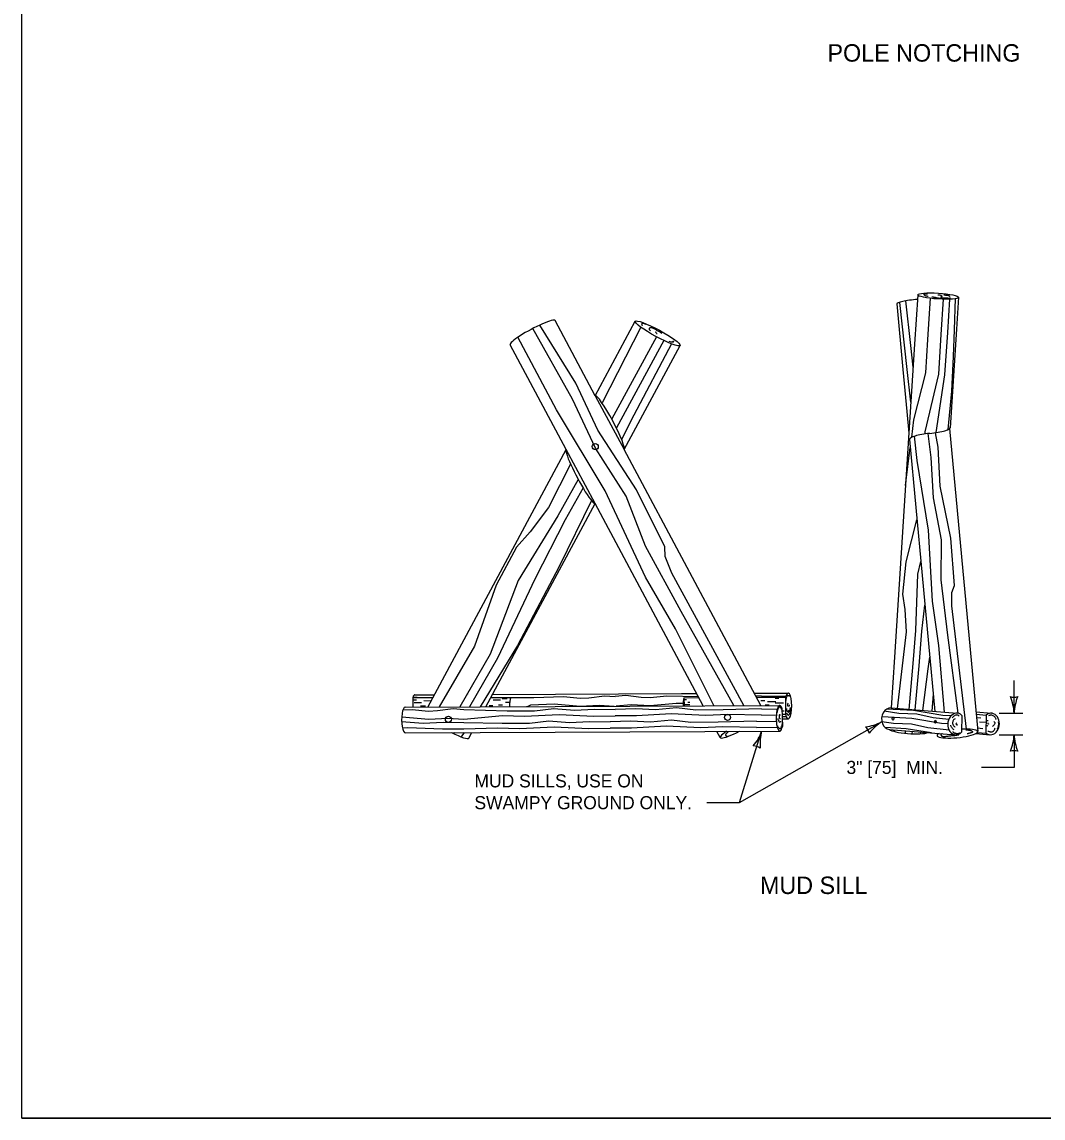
# Model space of a CAD drawing. Extents: x 49991.4 to 50021, y 49987.6 to 50011.4.
# Drawn here: x 49999.38 to 50004.07, y 49987.8 to 49992.83 of the extents above; entities that cross this region are included whole.
import ezdxf

# ---------------------------------------------------------------- set-up
doc = ezdxf.new("R2010")
doc.units = 0
for name, color, linetype in [('Level 1', 7, 'Continuous'), ('Level 2', 7, 'Continuous'), ('Level 3', 7, 'Continuous')]:
    doc.layers.add(name, color=color, linetype=linetype)

msp = doc.modelspace()

# ---------------------------------------------------------------- linework, layer by layer
at = {"layer": 'Level 1'}
for p, q in [((50003.4936, 49991.577), (50003.479, 49991.3507)), ((50003.6813, 49991.5654), (50003.6718, 49991.419)), ((50003.3977, 49991.5349), (50003.4257, 49991.2337)), ((50002.0141, 49991.1141), (50001.8296, 49991.4592)), ((50002.0141, 49991.1141), (50002.1974, 49991.4553)), ((50003.6718, 49991.419), (50003.6423, 49990.9664)), ((50001.8813, 49990.8669), (50001.624, 49991.3481)), ((50002.1461, 49990.8666), (50002.4032, 49991.3444)), ((50003.479, 49991.3507), (50003.3866, 49989.9146)), ((50003.4257, 49991.2337), (50003.4435, 49991.0416)), ((50002.0141, 49991.1141), (50002.1461, 49990.8666)), ((50003.4435, 49991.0416), (50003.4527, 49990.9426)), ((50003.6395, 49990.963), (50003.769, 49989.5724)), ((50003.4555, 49990.9128), (50003.5718, 49989.665)), ((50001.2462, 49989.6853), (50001.8813, 49990.8669)), ((50002.0134, 49990.6194), (50001.8813, 49990.8669)), ((50002.7737, 49989.6925), (50002.1461, 49990.8668)), ((50001.5121, 49989.6866), (50002.0134, 49990.6194)), ((50002.5094, 49989.6913), (50002.0134, 49990.6194)), ((50003.3866, 49989.9146), (50003.3716, 49989.6811)), ((50001.5425, 49989.7431), (50002.4104, 49989.7472)), ((50002.4105, 49989.7472), (50002.4793, 49989.7475)), ((50002.7437, 49989.7488), (50002.7587, 49989.7488)), ((50002.7587, 49989.7488), (50002.8992, 49989.7494)), ((50001.1769, 49989.7288), (50001.2697, 49989.7292)), ((50001.1769, 49989.7289), (50001.1769, 49989.6852)), ((50001.1769, 49989.7184), (50001.1941, 49989.7184)), ((50001.183, 49989.7054), (50001.2166, 49989.7054)), ((50001.1869, 49989.7415), (50001.2766, 49989.7419)), ((50001.2269, 49989.7152), (50001.2617, 49989.7143)), ((50001.5351, 49989.7294), (50001.6261, 49989.7294)), ((50001.5454, 49989.7175), (50001.579, 49989.7175)), ((50001.5704, 49989.6952), (50001.5883, 49989.6952)), ((50001.5863, 49989.7247), (50001.6096, 49989.7247)), ((50001.6022, 49989.7071), (50001.6213, 49989.7071)), ((50002.4212, 49989.728), (50002.4897, 49989.7282)), ((50002.4212, 49989.728), (50002.4221, 49989.6908)), ((50002.4214, 49989.719), (50002.4326, 49989.719)), ((50002.4249, 49989.6967), (50002.4474, 49989.6967)), ((50002.4386, 49989.7071), (50002.4476, 49989.7071)), ((50002.7542, 49989.7292), (50002.8871, 49989.7297)), ((50002.7745, 49989.7153), (50002.7927, 49989.7153)), ((50002.7933, 49989.6947), (50002.8115, 49989.6947)), ((50002.8044, 49989.7112), (50002.8425, 49989.7112)), ((50002.8389, 49989.7253), (50002.8571, 49989.7253)), ((50002.8399, 49989.7041), (50002.8781, 49989.7041)), ((50002.8871, 49989.7297), (50002.887, 49989.6518)), ((50003.5639, 49989.7441), (50003.5589, 49989.6661)), ((50001.1419, 49989.6848), (50002.8606, 49989.6929)), ((50001.2115, 49989.6908), (50001.2354, 49989.6908)), ((50001.5266, 49989.6918), (50001.5445, 49989.6918)), ((50002.8702, 49989.6815), (50002.873, 49989.5959)), ((50002.8706, 49989.6682), (50002.8815, 49989.6682)), ((50002.873, 49989.6518), (50002.887, 49989.6518)), ((50003.3715, 49989.6811), (50003.6753, 49989.6567)), ((50003.6965, 49989.6468), (50003.6952, 49989.5691)), ((50003.7606, 49989.6625), (50003.8327, 49989.6568)), ((50003.7615, 49989.6523), (50003.808, 49989.6485)), ((50003.808, 49989.6485), (50003.8066, 49989.5656)), ((50002.8718, 49989.6314), (50002.8995, 49989.6314)), ((50003.763, 49989.6365), (50003.7831, 49989.6349)), ((50003.7773, 49989.618), (50003.8074, 49989.6155)), ((50001.1424, 49989.5669), (50002.8606, 49989.5749)), ((50001.4345, 49989.5423), (50001.4485, 49989.5683)), ((50002.5876, 49989.545), (50002.5723, 49989.5736)), ((50003.363, 49989.5827), (50003.6674, 49989.5583)), ((50003.7602, 49989.5634), (50003.8248, 49989.5583)), ((50003.7672, 49989.5687), (50003.8066, 49989.5656)), ((50003.7674, 49989.589), (50003.7922, 49989.587))]:
    msp.add_line(p, q, dxfattribs=at)
msp.add_lwpolyline([(49999.3835, 49998.9992), (50016.7501, 49998.9992), (50016.7501, 49987.7988), (49999.3835, 49987.7988)], close=True, dxfattribs=at)
for points in [[(50003.5399, 49991.3723), (50003.552, 49991.5609)], [(50003.6019, 49991.3943), (50003.6124, 49991.5567)], [(50003.6313, 49991.4046), (50003.6412, 49991.5569)], [(50003.6622, 49991.4156), (50003.6677, 49991.5594)], [(50003.4457, 49991.2337), (50003.412, 49991.5424)], [(50003.4614, 49991.3445), (50003.4392, 49991.5487)], [(50002.6505, 49989.6919), (50002.4084, 49990.1237), (50002.2442, 49990.424), (50002.1561, 49990.6524), (50002.0147, 49990.8733), (50001.9096, 49991.0975), (50001.7277, 49991.4225)], [(50002.6964, 49989.6921), (50002.3656, 49990.3002), (50002.335, 49990.3753), (50002.3338, 49990.4207), (50002.2039, 49990.6827), (50002.0264, 49990.9553), (50001.925, 49991.1721), (50001.7591, 49991.438)], [(50002.2228, 49991.4283), (50002.0452, 49991.0812)], [(50003.5781, 49990.9445), (50003.6187, 49991.2098), (50003.6313, 49991.4046)], [(50003.6327, 49990.959), (50003.6507, 49991.1355), (50003.6576, 49991.2939), (50003.6622, 49991.4156)], [(50002.5588, 49989.6915), (50002.382, 49990.0438), (50002.2442, 49990.2812), (50002.0589, 49990.6774), (50001.8362, 49991.0489), (50001.659, 49991.3819)], [(50002.2945, 49991.3845), (50002.0896, 49991.0073)], [(50002.3287, 49991.3672), (50002.111, 49990.9661)], [(50003.4671, 49990.9235), (50003.4752, 49991.0037), (50003.5301, 49991.2188), (50003.5399, 49991.3723)], [(50003.5281, 49990.9385), (50003.5285, 49990.9486), (50003.5902, 49991.2126), (50003.6019, 49991.3943)], [(50002.3636, 49991.352), (50002.1908, 49991.0247), (50002.135, 49990.9132)], [(50003.4722, 49991.2444), (50003.4614, 49991.3445)], [(50003.4619, 49991.0847), (50003.4457, 49991.2337)], [(50003.6167, 49989.6614), (50003.5908, 49989.967), (50003.5612, 49990.1703), (50003.5424, 49990.4968), (50003.4911, 49990.8164), (50003.4789, 49990.928)], [(50003.6787, 49989.6563), (50003.6315, 49990.0154), (50003.6009, 49990.2695), (50003.6031, 49990.4525), (50003.5662, 49990.6451), (50003.5553, 49990.8302), (50003.541, 49990.9401)], [(50003.7177, 49989.5843), (50003.6508, 49990.1496), (50003.6503, 49990.2105), (50003.6622, 49990.2423), (50003.6448, 49990.4603), (50003.5972, 49990.6992), (50003.587, 49990.8776), (50003.5751, 49990.9441)], [(50003.4373, 49990.7017), (50003.4589, 49990.8765)], [(50001.9012, 49990.7999), (50001.7992, 49990.6006), (50001.7159, 49990.4895), (50001.6529, 49990.4194), (50001.56, 49990.245), (50001.4604, 49989.9652), (50001.2986, 49989.6856)], [(50001.936, 49990.7296), (50001.8422, 49990.5625), (50001.6599, 49990.2663), (50001.5323, 49989.9273), (50001.3927, 49989.686)], [(50001.9581, 49990.6906), (50001.8761, 49990.5449), (50001.7361, 49990.2727), (50001.5658, 49989.9091), (50001.4367, 49989.6862)], [(50001.9963, 49990.6331), (50001.8491, 49990.3297), (50001.6568, 49989.9676), (50001.4856, 49989.6864)], [(50003.4263, 49989.9005), (50003.4415, 49990.0299), (50003.436, 49990.1335), (50003.4257, 49990.2033), (50003.4407, 49990.3508), (50003.4899, 49990.5436)], [(50003.4722, 49989.8843), (50003.4842, 49990.0357), (50003.494, 49990.2957), (50003.5076, 49990.3538)], [(50003.5001, 49989.8744), (50003.5126, 49990.0328), (50003.5264, 49990.1525)], [(50003.4003, 49989.6788), (50003.4263, 49989.9005)], [(50003.541, 49989.8599), (50003.5486, 49989.914)], [(50003.454, 49989.6745), (50003.4722, 49989.8843)], [(50003.4825, 49989.6722), (50003.5001, 49989.8744)], [(50003.5169, 49989.6694), (50003.541, 49989.8599)], [(50001.1772, 49989.7298), (50001.1968, 49989.7306), (50001.2139, 49989.7289)], [(50001.4329, 49989.7438), (50001.4329, 49989.744)], [(50001.6259, 49989.7289), (50001.7317, 49989.7284), (50001.8683, 49989.7335), (50001.9441, 49989.7264), (50001.9852, 49989.7281), (50002.056, 49989.7373), (50002.1051, 49989.7328)], [(50001.6979, 49989.6874), (50001.7038, 49989.6881), (50001.7185, 49989.6956), (50001.8254, 49989.6991), (50001.9442, 49989.6891), (50002.0314, 49989.6939), (50002.1008, 49989.6894)], [(50002.4879, 49989.7314), (50002.3419, 49989.7356), (50002.2662, 49989.7277), (50002.2251, 49989.7291), (50002.1542, 49989.7377), (50002.1051, 49989.7328)], [(50002.4174, 49989.7008), (50002.3851, 49989.7016), (50002.2664, 49989.6905), (50002.1791, 49989.6946), (50002.1098, 49989.6894)], [(50002.7767, 49989.7358), (50002.7508, 49989.7354)], [(50002.7767, 49989.7358), (50002.8887, 49989.7352)], [(50001.132, 49989.6725), (50001.1739, 49989.674), (50001.2496, 49989.6669), (50001.2908, 49989.6686), (50001.3616, 49989.6778), (50001.4108, 49989.6734)], [(50001.4108, 49989.6734), (50001.61, 49989.6682), (50001.7352, 49989.6673), (50001.824, 49989.6783), (50001.9195, 49989.6711), (50002.0102, 49989.6759), (50002.1054, 49989.6743)], [(50001.4109, 49989.6296), (50001.5887, 49989.6457), (50001.6892, 49989.6425), (50001.8489, 49989.6513), (50002.007, 49989.644), (50002.1055, 49989.6444)], [(50002.7769, 49989.6772), (50002.6008, 49989.6726), (50002.4757, 49989.6706), (50002.3868, 49989.6808), (50002.2912, 49989.6727), (50002.2006, 49989.6767), (50002.1054, 49989.6743)], [(50002.7771, 49989.6474), (50002.6222, 49989.6502), (50002.5218, 49989.6462), (50002.3621, 49989.6536), (50002.204, 49989.6448), (50002.1055, 49989.6444)], [(50002.7769, 49989.6772), (50002.8492, 49989.6759)], [(50002.7771, 49989.6474), (50002.8449, 49989.6492)], [(50003.6359, 49989.6283), (50003.5649, 49989.6352), (50003.4899, 49989.6528), (50003.4074, 49989.655), (50003.3397, 49989.6658)], [(50003.6459, 49989.6443), (50003.6095, 49989.6469), (50003.4737, 49989.6689), (50003.3511, 49989.676)], [(50001.1258, 49989.6192), (50001.2252, 49989.6117), (50001.3157, 49989.6164), (50001.4109, 49989.6148)], [(50001.1262, 49989.64), (50001.2498, 49989.6296), (50001.337, 49989.6344), (50001.4109, 49989.6296)], [(50001.4109, 49989.6148), (50001.5871, 49989.6117), (50001.7123, 49989.6107), (50001.801, 49989.6218), (50001.8966, 49989.6145), (50001.9873, 49989.6194), (50002.0825, 49989.6177)], [(50001.411, 49989.5849), (50001.5658, 49989.5892), (50001.6662, 49989.586), (50001.8259, 49989.5948), (50001.9841, 49989.5874), (50002.0826, 49989.5878)], [(50002.754, 49989.6207), (50002.5779, 49989.616), (50002.4528, 49989.614), (50002.3638, 49989.6243), (50002.2682, 49989.6161), (50002.1777, 49989.6202), (50002.0825, 49989.6177)], [(50002.7542, 49989.5908), (50002.5993, 49989.5937), (50002.4989, 49989.5897), (50002.3392, 49989.5971), (50002.1811, 49989.5883), (50002.0826, 49989.5878)], [(50002.754, 49989.6207), (50002.8449, 49989.619)], [(50002.8715, 49989.641), (50002.8902, 49989.6415)], [(50003.6316, 49989.6077), (50003.602, 49989.6099), (50003.4662, 49989.6318), (50003.3301, 49989.6397), (50003.3286, 49989.6399)], [(50003.6378, 49989.5796), (50003.5398, 49989.5892), (50003.4648, 49989.6065), (50003.3822, 49989.6089), (50003.3292, 49989.6174)], [(50001.129, 49989.5904), (50001.1544, 49989.5919), (50001.3125, 49989.5845), (50001.411, 49989.5849)], [(50001.3681, 49989.568), (50001.365, 49989.5626)], [(50001.412, 49989.5682), (50001.3996, 49989.5481)], [(50002.7542, 49989.5908), (50002.8488, 49989.5934)], [(50003.5564, 49989.5672), (50003.441, 49989.5858), (50003.3437, 49989.5914)], [(50003.3878, 49989.5725), (50003.3887, 49989.5806)], [(50003.4369, 49989.5641), (50003.4383, 49989.5766)], [(50003.4684, 49989.5619), (50003.4699, 49989.5741)], [(50003.5073, 49989.5624), (50003.5083, 49989.571)]]:
    msp.add_lwpolyline(points, dxfattribs=at)
for centre in [(50002.0141, 49990.8804), (50002.621, 49989.6374), (50001.3403, 49989.6288)]:
    msp.add_circle(centre, 0.0139, dxfattribs=at)
for centre, major_axis, ratio, start_param, end_param in [((50003.4912, 49991.5421), (0.0936, 0.0072), 0.143064, 1.548914, 3.140392), ((50001.7269, 49991.4035), (-0.1029, -0.0554), 0.139914, 3.139201, 6.283242), ((50002.0801, 49990.9903), (-0.066, 0.1238), 0.116361, 3.145361, 6.285545), ((50003.5499, 49990.9601), (0.0932, 0.0089), 0.201992, 4.679863, 6.355951), ((50003.549, 49990.9219), (0.0934, 0.0089), 0.201542, 1.555621, 3.157543), ((50001.9473, 49990.7431), (-0.066, 0.1238), 0.116361, 0.000894, 3.157998), ((50002.8992, 49989.6904), (0, 0.059), 0.275041, 2.285093, 7.125252), ((50001.1869, 49989.6825), (0, 0.059), 0.275041, 0.000018, 0.664042), ((50001.6361, 49989.6831), (0, 0.059), 0.275041, 0.667259, 1.502637), ((50002.4332, 49989.6883), (0, 0.059), 0.275041, 0.832502, 1.528499), ((50002.8606, 49989.6339), (0, 0.059), 0.275041, 5.650695, 10.294257), ((50001.1419, 49989.6259), (0, 0.059), 0.275041, 0.000018, 3.17879), ((50003.3676, 49989.6319), (0.0039, 0.0492), 0.803113, 6.282757, 9.424573), ((50003.6713, 49989.6075), (0.0039, 0.0492), 0.803113, 5.697673, 10.16742), ((50003.8287, 49989.6075), (0.0039, 0.0492), 0.803113, 2.649394, 6.932864), ((50001.3316, 49989.5976), (-0.1029, 0.0554), 0.139914, 1.86222, 3.141392), ((50002.6907, 49989.5999), (-0.1029, -0.0554), 0.139914, 5.440424, 7.640142), ((50003.4558, 49989.5808), (-0.0937, 0.0061), 0.194104, 0.229025, 2.752598), ((50003.6753, 49989.5635), (0.0932, 0.0089), 0.201992, 2.665922, 7.614822)]:
    msp.add_ellipse(centre, major_axis=major_axis, ratio=ratio, start_param=start_param, end_param=end_param, dxfattribs=at)
for centre, major_axis, ratio in [((50003.5875, 49991.5712), (0.0937, -0.0058), 0.143064), ((50002.3004, 49991.3999), (-0.1029, 0.0554), 0.139914), ((50003.38, 49989.6318), (0, 0.00692), 0.506883), ((50003.5749, 49989.6175), (0, 0.00692), 0.506883)]:
    msp.add_ellipse(centre, major_axis=major_axis, ratio=ratio, dxfattribs=at)
for points in [[(50003.5421, 49991.5689), (50003.5365, 49991.57), (50003.5308, 49991.5713), (50003.5264, 49991.574), (50003.5234, 49991.5766), (50003.5239, 49991.5798), (50003.5279, 49991.5807), (50003.5323, 49991.5817), (50003.5382, 49991.5813)], [(50003.559, 49991.5672), (50003.5643, 49991.5672), (50003.5671, 49991.5662), (50003.5731, 49991.5655), (50003.5779, 49991.5643), (50003.5836, 49991.5634), (50003.5902, 49991.5623), (50003.5938, 49991.5623), (50003.6033, 49991.563), (50003.6034, 49991.563), (50003.6095, 49991.5634), (50003.6169, 49991.563), (50003.6275, 49991.563), (50003.6335, 49991.5619), (50003.6387, 49991.5623), (50003.6435, 49991.5636)], [(50003.5991, 49991.568), (50003.6046, 49991.5697), (50003.606, 49991.57), (50003.6034, 49991.5728), (50003.6024, 49991.5735), (50003.5971, 49991.575), (50003.592, 49991.5756), (50003.5876, 49991.5756), (50003.5871, 49991.5761)], [(50003.6134, 49991.5774), (50003.6158, 49991.5766), (50003.6192, 49991.5763), (50003.6235, 49991.5756), (50003.6275, 49991.5755), (50003.6327, 49991.5743), (50003.635, 49991.574), (50003.6374, 49991.5725), (50003.6382, 49991.5711), (50003.6387, 49991.57), (50003.6387, 49991.5697)], [(50002.2471, 49991.44), (50002.2397, 49991.4433), (50002.2315, 49991.4454), (50002.2274, 49991.4437), (50002.2268, 49991.4422), (50002.2284, 49991.4379), (50002.229, 49991.4365)], [(50002.319, 49991.3998), (50002.3113, 49991.4056), (50002.2991, 49991.4122), (50002.2877, 49991.4189), (50002.2762, 49991.4242), (50002.2697, 49991.4257), (50002.2643, 49991.4248), (50002.2619, 49991.4223), (50002.2613, 49991.419), (50002.263, 49991.4164), (50002.2673, 49991.4118)], [(50002.293, 49991.4056), (50002.2911, 49991.4061), (50002.2908, 49991.405), (50002.2932, 49991.4022), (50002.2945, 49991.4012), (50002.2971, 49991.399), (50002.2983, 49991.3993)], [(50002.3705, 49991.3654), (50002.3726, 49991.3631), (50002.3726, 49991.3606), (50002.3698, 49991.359), (50002.3627, 49991.3597), (50002.3537, 49991.3629)], [(50002.8885, 49989.7053), (50002.8885, 49989.7134), (50002.8893, 49989.7161), (50002.8905, 49989.7237), (50002.8916, 49989.7283), (50002.8947, 49989.7345), (50002.8979, 49989.7383), (50002.9022, 49989.7383), (50002.9044, 49989.7348), (50002.9056, 49989.7328)], [(50002.8999, 49989.7036), (50002.8981, 49989.7015), (50002.8965, 49989.6977), (50002.8956, 49989.6928), (50002.897, 49989.6885)], [(50002.9038, 49989.695), (50002.9044, 49989.6928), (50002.903, 49989.6885), (50002.9022, 49989.6874), (50002.9004, 49989.6871)], [(50002.8495, 49989.6598), (50002.8495, 49989.662), (50002.8495, 49989.6644), (50002.8503, 49989.6687), (50002.8517, 49989.6703), (50002.8523, 49989.6731), (50002.8526, 49989.6755), (50002.854, 49989.6785), (50002.856, 49989.6817), (50002.8574, 49989.685), (50002.86, 49989.6863), (50002.8623, 49989.6861), (50002.864, 49989.6836), (50002.8649, 49989.6814), (50002.8665, 49989.6785), (50002.8683, 49989.675)], [(50002.8635, 49989.6472), (50002.8617, 49989.6491), (50002.8589, 49989.6493), (50002.8581, 49989.6477), (50002.8578, 49989.6466), (50002.8575, 49989.6436), (50002.8572, 49989.6409), (50002.8583, 49989.6377), (50002.8586, 49989.6353), (50002.8595, 49989.6328), (50002.8609, 49989.6323), (50002.8635, 49989.6331)], [(50002.8913, 49989.6785), (50002.8916, 49989.6739), (50002.8925, 49989.6702), (50002.895, 49989.6661), (50002.8976, 49989.6631), (50002.8996, 49989.6623), (50002.901, 49989.6626), (50002.9019, 49989.6656), (50002.9039, 49989.6718)], [(50002.8928, 49989.6568), (50002.8936, 49989.6544), (50002.895, 49989.6511), (50002.8973, 49989.6495), (50002.9007, 49989.6479), (50002.9019, 49989.649), (50002.9047, 49989.6517), (50002.9047, 49989.6523), (50002.9064, 49989.6549), (50002.9078, 49989.6598), (50002.9087, 49989.6652), (50002.9084, 49989.6701), (50002.9101, 49989.6828)], [(50003.684, 49989.644), (50003.6811, 49989.6464), (50003.6779, 49989.6479), (50003.6751, 49989.6486), (50003.6702, 49989.6485), (50003.6642, 49989.6466), (50003.6592, 49989.6429), (50003.6551, 49989.6391), (50003.6517, 49989.634)], [(50003.8199, 49989.646), (50003.8257, 49989.6483), (50003.8303, 49989.6491), (50003.8353, 49989.6481), (50003.842, 49989.6446), (50003.8467, 49989.6405), (50003.849, 49989.6369), (50003.852, 49989.6311), (50003.8528, 49989.6277)], [(50002.8721, 49989.6223), (50002.872, 49989.6179), (50002.872, 49989.6147), (50002.8711, 49989.6066), (50002.8706, 49989.6028), (50002.8686, 49989.5979), (50002.8672, 49989.5933), (50002.8666, 49989.5893), (50002.8623, 49989.586), (50002.8589, 49989.5863), (50002.8566, 49989.5893), (50002.854, 49989.592), (50002.8515, 49989.5952), (50002.8515, 49989.5963), (50002.8515, 49989.599)], [(50002.8515, 49989.6328), (50002.8524, 49989.6285), (50002.856, 49989.6199), (50002.8595, 49989.6161), (50002.8646, 49989.6187), (50002.866, 49989.6204)], [(50003.6609, 49989.58), (50003.6558, 49989.5841), (50003.6537, 49989.5873), (50003.6504, 49989.5909), (50003.6467, 49989.5956), (50003.6451, 49989.6022)], [(50003.6662, 49989.6315), (50003.6599, 49989.6282), (50003.657, 49989.6232), (50003.654, 49989.6167), (50003.6531, 49989.6101), (50003.6558, 49989.6022), (50003.6593, 49989.5976), (50003.6643, 49989.5931)], [(50003.6736, 49989.6129), (50003.6693, 49989.6093), (50003.6696, 49989.6063), (50003.6713, 49989.6043), (50003.6737, 49989.6029), (50003.676, 49989.6037), (50003.6769, 49989.6051)], [(50003.8157, 49989.5981), (50003.813, 49989.5988), (50003.8098, 49989.5995), (50003.8072, 49989.6005)], [(50003.8075, 49989.6203), (50003.8076, 49989.6204), (50003.8114, 49989.6231), (50003.8145, 49989.6236), (50003.8171, 49989.6237)], [(50003.8167, 49989.6118), (50003.8149, 49989.6105), (50003.8147, 49989.6091), (50003.8157, 49989.6081), (50003.818, 49989.6076), (50003.8189, 49989.6071)], [(50003.8427, 49989.6195), (50003.8469, 49989.6136), (50003.8477, 49989.6101), (50003.8441, 49989.6032), (50003.8392, 49989.5974), (50003.8363, 49989.5962)], [(50003.8588, 49989.5842), (50003.8603, 49989.5867), (50003.8627, 49989.5917), (50003.8638, 49989.5964), (50003.8657, 49989.6046), (50003.8656, 49989.6118), (50003.8637, 49989.6175)], [(50002.6246, 49989.5708), (50002.6182, 49989.5658), (50002.6126, 49989.5595), (50002.612, 49989.5552), (50002.6133, 49989.5539), (50002.6178, 49989.5534), (50002.6193, 49989.5533)], [(50003.6057, 49989.5621), (50003.6035, 49989.5611), (50003.6008, 49989.559), (50003.6001, 49989.5568), (50003.6013, 49989.5547), (50003.6027, 49989.5526), (50003.605, 49989.5516), (50003.6083, 49989.5507), (50003.6141, 49989.5505), (50003.6224, 49989.5505), (50003.6272, 49989.5513), (50003.6327, 49989.5518), (50003.6421, 49989.5533), (50003.6505, 49989.5539), (50003.6571, 49989.5544), (50003.6645, 49989.555), (50003.6735, 49989.5565), (50003.6816, 49989.5578)], [(50003.6875, 49989.5663), (50003.6838, 49989.5646), (50003.6772, 49989.5627), (50003.6747, 49989.5624), (50003.6693, 49989.563), (50003.6649, 49989.5645), (50003.66, 49989.5673), (50003.6566, 49989.5704), (50003.6555, 49989.5725)], [(50003.6624, 49989.5591), (50003.6591, 49989.559), (50003.6564, 49989.559), (50003.6555, 49989.559)], [(50003.714, 49989.5804), (50003.7187, 49989.5804), (50003.7231, 49989.5804), (50003.7264, 49989.5797), (50003.7293, 49989.579), (50003.7341, 49989.5783), (50003.7364, 49989.5774), (50003.7401, 49989.5762), (50003.7415, 49989.5754), (50003.7428, 49989.5743), (50003.7443, 49989.5728), (50003.7452, 49989.5706), (50003.7445, 49989.5695), (50003.742, 49989.568), (50003.7364, 49989.5664), (50003.7346, 49989.5658), (50003.7279, 49989.5638), (50003.7255, 49989.5632), (50003.7224, 49989.5621), (50003.7209, 49989.5621)], [(50003.8154, 49989.5749), (50003.8222, 49989.5735), (50003.8264, 49989.5721), (50003.8325, 49989.5718), (50003.8382, 49989.573), (50003.8409, 49989.575), (50003.8445, 49989.5787), (50003.8474, 49989.5838), (50003.8484, 49989.5881)]]:
    msp.add_spline(points, degree=3, dxfattribs=at)
at = {"layer": 'Level 3'}
for p, q in [((50003.9357, 49989.6568), (50003.9357, 49989.8068)), ((50003.8674, 49989.6568), (50003.9757, 49989.6568)), ((50002.6757, 49989.2463), (50002.7775, 49989.5746)), ((50003.8674, 49989.5581), (50003.9757, 49989.5581)), ((49999.3835, 49987.7988), (50016.7501, 49987.7988))]:
    msp.add_line(p, q, dxfattribs=at)
for points in [[(50002.5257, 49989.2463), (50002.6757, 49989.2463), (50003.3292, 49989.6174)], [(50003.9357, 49989.5581), (50003.9357, 49989.4081), (50003.7857, 49989.4081)]]:
    msp.add_lwpolyline(points, dxfattribs=at)
for centre, radius, start, end in [((50003.9357, 49989.785), 0.0548, 252.1388, 287.8612), ((50003.703, 49989.6453), 0.233, 2.8273, 22.0772), ((50004.1578, 49989.6476), 0.2223, 157.456, 177.6395), ((50003.2274, 49989.8151), 0.2223, 277.049, 297.2325), ((50003.2177, 49989.5541), 0.0548, 11.7318, 47.4542), ((50003.4541, 49989.4207), 0.233, 122.4203, 141.6702), ((50002.5681, 49989.6491), 0.2223, 320.2254, 340.4089), ((50003.0032, 49989.5166), 0.233, 165.5967, 184.8465), ((50003.7136, 49989.5673), 0.2223, 337.456, 357.6395), ((50004.1684, 49989.5696), 0.233, 182.8273, 202.0772), ((50002.7396, 49989.4521), 0.0548, 54.9082, 90.6306), ((50003.9357, 49989.4299), 0.0548, 72.1388, 107.8612)]:
    msp.add_arc(centre, radius, start, end, dxfattribs=at)

# ---------------------------------------------------------------- texts
at = {"layer": 'Level 2'}
for s, height, p in [('POLE NOTCHING', 0.08, (50003.0796, 49992.6471)), ('MUD SILLS, USE ON ', 0.06, (50001.4596, 49989.3163)), ('SWAMPY GROUND ONLY.', 0.06, (50001.4596, 49989.2163)), ('MUD SILL', 0.08, (50002.7699, 49988.8271))]:
    msp.add_text(s, height=height, dxfattribs=at).set_placement(p)
msp.add_text('3" [75]  MIN.', height=0.06, rotation=359.9993, dxfattribs=at).set_placement((50003.1667, 49989.3781))

doc.saveas('drawing.dxf')
